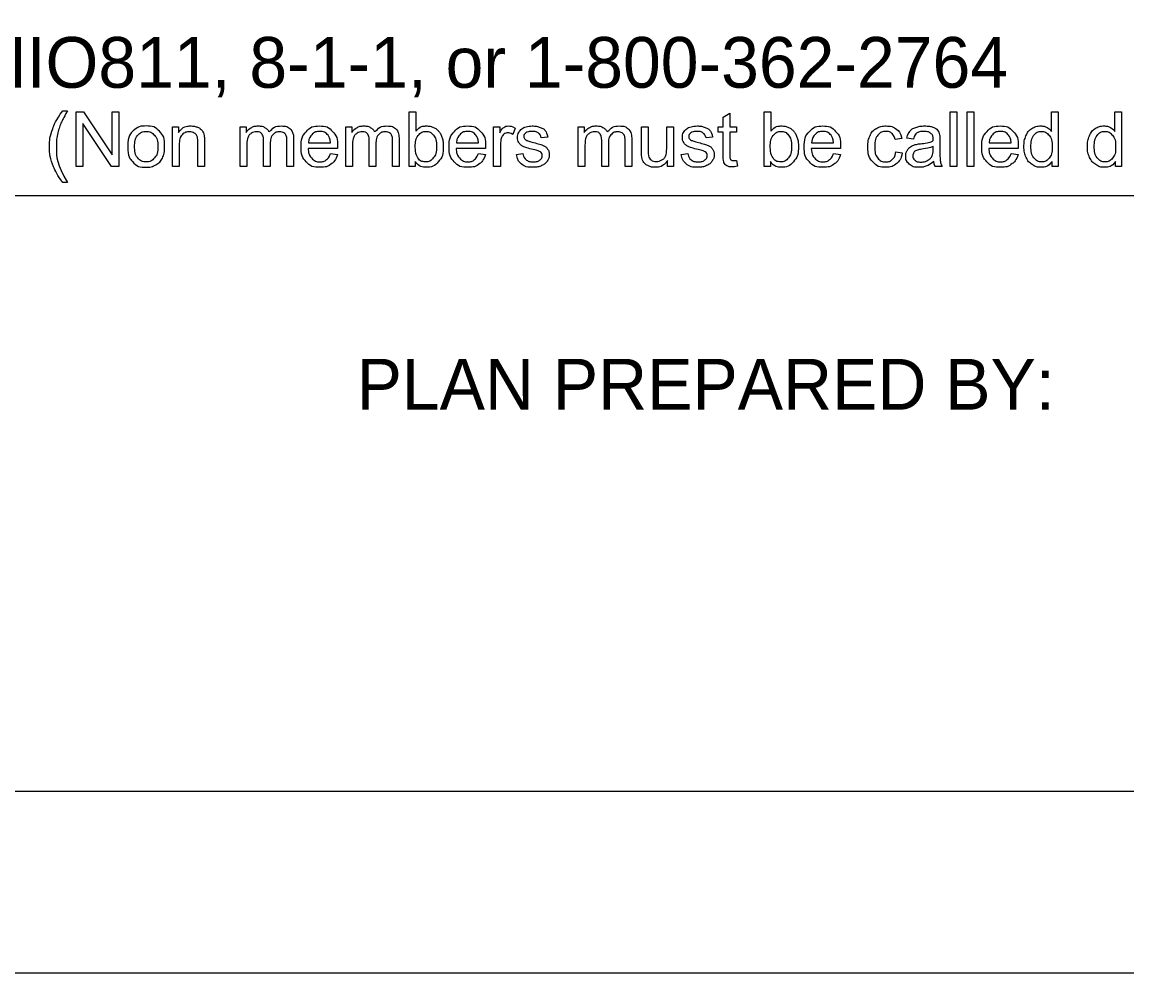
# Model space of a CAD drawing. Extents: x 0 to 34, y -1.6 to 22.
# Drawn here: x 2.69 to 5.736, y 0 to 2.622 of the extents above; entities that cross this region are included whole.
import ezdxf

# ---------------------------------------------------------------- set-up
doc = ezdxf.new("R2010")
doc.units = 0
for name, color, linetype in [('SH_Border', 7, 'Continuous'), ('SH_Cut_Line', 7, 'Continuous'), ('SH_Data', 7, 'Continuous'), ('SH_Text', 7, 'Continuous')]:
    doc.layers.add(name, color=color, linetype=linetype)

msp = doc.modelspace()

# ---------------------------------------------------------------- linework, layer by layer
at = {"layer": 'SH_Border'}
msp.add_lwpolyline([(1.5, 21.5), (33.5, 21.5), (33.5, 0.5), (1.5, 0.5)], close=True, dxfattribs=at)
at = {"layer": 'SH_Cut_Line'}
msp.add_lwpolyline([(0, 0), (34, 0), (34, 22), (0, 22)], close=True, dxfattribs=at)
at = {"layer": 'SH_Data'}
msp.add_line((6.6275, 2.1428), (2.3775, 2.1428), dxfattribs=at)
at = {"layer": 'SH_Text'}
for points in [[(2.8021, 2.3766), (2.8153, 2.3766)], [(2.8389, 2.2239), (2.8389, 2.3741), (2.8592, 2.3741), (2.9382, 2.2561), (2.9382, 2.3741), (2.9572, 2.3741), (2.9572, 2.2239), (2.9369, 2.2239), (2.8579, 2.3419), (2.8579, 2.2239), (2.8389, 2.2239)], [(3.7743, 2.2239), (3.7573, 2.2239), (3.7573, 2.3741), (3.7757, 2.3741), (3.7757, 2.3206)], [(4.6233, 2.2558), (4.6233, 2.3185), (4.6097, 2.3185), (4.6097, 2.3328), (4.6233, 2.3328), (4.6233, 2.3597), (4.6417, 2.3708), (4.6417, 2.3328), (4.6601, 2.3328), (4.6601, 2.3185), (4.6417, 2.3185), (4.6417, 2.2547)], [(4.7534, 2.2239), (4.7363, 2.2239), (4.7363, 2.3741), (4.7548, 2.3741), (4.7548, 2.3206)], [(5.2491, 2.2239), (5.2491, 2.3741), (5.2675, 2.3741), (5.2675, 2.2239), (5.2491, 2.2239)], [(5.2956, 2.2239), (5.2956, 2.3741), (5.3141, 2.3741), (5.3141, 2.2239), (5.2956, 2.2239)], [(5.5285, 2.3202), (5.5285, 2.3741), (5.5469, 2.3741), (5.5469, 2.2239), (5.5299, 2.2239)], [(5.7034, 2.3202), (5.7034, 2.3741), (5.7218, 2.3741), (5.7218, 2.2239), (5.7048, 2.2239)], [(3.1048, 2.2239), (3.1048, 2.3328), (3.1214, 2.3328), (3.1214, 2.3173)], [(3.2912, 2.2239), (3.2912, 2.3328), (3.3077, 2.3328), (3.3077, 2.3174)], [(3.5826, 2.2239), (3.5826, 2.3328), (3.5991, 2.3328), (3.5991, 2.3174)], [(3.9904, 2.2239), (3.9904, 2.3328), (4.007, 2.3328), (4.007, 2.3163)], [(4.0495, 2.3293), (4.043, 2.3122)], [(4.2236, 2.2239), (4.2236, 2.3328), (4.2401, 2.3328), (4.2401, 2.3174)], [(4.3979, 2.2654), (4.3979, 2.3328), (4.4164, 2.3328), (4.4164, 2.2724)], [(4.4676, 2.2745), (4.4676, 2.3328), (4.4861, 2.3328), (4.4861, 2.2239), (4.4696, 2.2239)], [(3.1932, 2.2908), (3.1932, 2.2239), (3.1748, 2.2239), (3.1748, 2.2901)], [(3.3743, 2.2871), (3.3743, 2.2239), (3.3559, 2.2239), (3.3559, 2.2946)], [(3.4388, 2.2986), (3.4388, 2.2239), (3.4203, 2.2239), (3.4203, 2.2924)], [(3.4799, 2.2887), (3.5406, 2.2887)], [(3.6657, 2.2871), (3.6657, 2.2239), (3.6473, 2.2239), (3.6473, 2.2946)], [(3.7301, 2.2986), (3.7301, 2.2239), (3.7117, 2.2239), (3.7117, 2.2924)], [(3.8879, 2.2887), (3.9486, 2.2887)], [(4.1394, 2.3046), (4.1213, 2.3022)], [(4.3067, 2.2871), (4.3067, 2.2239), (4.2883, 2.2239), (4.2883, 2.2946)], [(4.3711, 2.2986), (4.3711, 2.2239), (4.3527, 2.2239), (4.3527, 2.2924)], [(4.594, 2.3046), (4.5759, 2.3022)], [(4.8669, 2.2887), (4.9277, 2.2887)], [(5.1154, 2.3007), (5.0974, 2.298)], [(5.1479, 2.2992), (5.1298, 2.3016)], [(5.2209, 2.2941), (5.2209, 2.2695)], [(5.3565, 2.2887), (5.4173, 2.2887)], [(3.1233, 2.2833), (3.1233, 2.2239), (3.1048, 2.2239)], [(3.3097, 2.2803), (3.3097, 2.2239), (3.2912, 2.2239)], [(3.56, 2.2736), (3.4788, 2.2736)], [(3.5404, 2.2591), (3.5595, 2.2567)], [(3.601, 2.2803), (3.601, 2.2239), (3.5826, 2.2239)], [(3.968, 2.2736), (3.8868, 2.2736)], [(3.9484, 2.2591), (3.9675, 2.2567)], [(4.0088, 2.2809), (4.0088, 2.2239), (3.9904, 2.2239)], [(4.053, 2.2564), (4.0712, 2.2593)], [(4.242, 2.2803), (4.242, 2.2239), (4.2236, 2.2239)], [(4.5076, 2.2564), (4.5258, 2.2593)], [(4.947, 2.2736), (4.8659, 2.2736)], [(4.9275, 2.2591), (4.9465, 2.2567)], [(5.099, 2.2638), (5.1171, 2.2613)], [(5.2023, 2.2718), (5.2024, 2.2785)], [(5.4366, 2.2736), (5.3555, 2.2736)], [(5.4171, 2.2591), (5.4361, 2.2567)], [(3.7743, 2.2375), (3.7743, 2.2239)], [(4.4696, 2.2239), (4.4696, 2.24)], [(4.6601, 2.2404), (4.6628, 2.2241)], [(4.7534, 2.2375), (4.7534, 2.2239)], [(5.2267, 2.2239), (5.2075, 2.2239)], [(5.5299, 2.2239), (5.5299, 2.2376)], [(5.7048, 2.2239), (5.7048, 2.2376)], [(2.8153, 2.1798), (2.8021, 2.1798)]]:
    msp.add_lwpolyline(points, dxfattribs=at)
for points, degree in [([(2.8021, 2.1798), (2.7869, 2.199), (2.7763, 2.2248), (2.7657, 2.2506), (2.7657, 2.2783), (2.7657, 2.3026), (2.7736, 2.325), (2.7829, 2.3509), (2.8021, 2.3766)], 3), ([(2.8153, 2.3766), (2.8029, 2.3553), (2.7989, 2.3462), (2.7927, 2.332), (2.7891, 2.3167), (2.7847, 2.2975), (2.7847, 2.2782), (2.7847, 2.2289), (2.8153, 2.1798)], 3), ([(2.9814, 2.2783), (2.9814, 2.3085), (2.9981, 2.3231), (3.0122, 2.3352), (3.0323, 2.3352), (3.0547, 2.3352), (3.069, 2.3205), (3.0832, 2.3058), (3.0832, 2.2799), (3.0832, 2.2589), (3.0769, 2.2469), (3.0706, 2.2348), (3.0586, 2.2282), (3.0466, 2.2215), (3.0323, 2.2215), (3.0095, 2.2215), (2.9954, 2.2362), (2.9814, 2.2508), (2.9814, 2.2783)], 3), ([(3.0003, 2.2783), (3.0003, 2.2574), (3.0094, 2.247), (3.0185, 2.2366), (3.0323, 2.2366), (3.046, 2.2366), (3.0551, 2.2471), (3.0642, 2.2575), (3.0642, 2.279), (3.0642, 2.2991), (3.0551, 2.3095), (3.0459, 2.3199), (3.0323, 2.3199), (3.0185, 2.3199), (3.0094, 2.3096), (3.0003, 2.2992), (3.0003, 2.2783)], 3), ([(3.1214, 2.3173), (3.1334, 2.3352), (3.156, 2.3352), (3.1659, 2.3352), (3.1741, 2.3316), (3.1823, 2.3281), (3.1864, 2.3224), (3.1905, 2.3166), (3.1922, 2.3087), (3.1932, 2.3036), (3.1932, 2.2908)], 3), ([(3.1748, 2.2901), (3.1748, 2.3013), (3.1726, 2.3069), (3.1705, 2.3125), (3.165, 2.3158), (3.1595, 2.3191), (3.1521, 2.3191), (3.1404, 2.3191), (3.1318, 2.3117), (3.1233, 2.3042), (3.1233, 2.2833)], 3), ([(3.3077, 2.3174), (3.3128, 2.3254), (3.3214, 2.3303), (3.3299, 2.3352), (3.3407, 2.3352), (3.3528, 2.3352), (3.3606, 2.3301), (3.3683, 2.3251), (3.3715, 2.3161), (3.3844, 2.3352), (3.4051, 2.3352), (3.4213, 2.3352), (3.43, 2.3262), (3.4388, 2.3172), (3.4388, 2.2986)], 3), ([(3.3559, 2.2946), (3.3559, 2.3069), (3.3514, 2.313), (3.3469, 2.3191), (3.3366, 2.3191), (3.3288, 2.3191), (3.3222, 2.315), (3.3156, 2.311), (3.3126, 2.3031), (3.3097, 2.2952), (3.3097, 2.2803)], 3), ([(3.4203, 2.2924), (3.4203, 2.3035), (3.4185, 2.3083), (3.4168, 2.3132), (3.412, 2.3162), (3.4073, 2.3191), (3.401, 2.3191), (3.3895, 2.3191), (3.3819, 2.3115), (3.3743, 2.3039), (3.3743, 2.2871)], 3), ([(3.5595, 2.2567), (3.555, 2.24), (3.5428, 2.2307), (3.5306, 2.2215), (3.5117, 2.2215), (3.4878, 2.2215), (3.4738, 2.2362), (3.4598, 2.2509), (3.4598, 2.2774), (3.4598, 2.3049), (3.474, 2.32), (3.4881, 2.3352), (3.5106, 2.3352), (3.5324, 2.3352), (3.5463, 2.3203), (3.5601, 2.3055), (3.5601, 2.2785), (3.5601, 2.2769), (3.56, 2.2736)], 3), ([(3.5406, 2.2887), (3.5394, 2.3025), (3.5337, 2.3094), (3.5249, 2.3201), (3.5108, 2.3201), (3.4981, 2.3201), (3.4894, 2.3115), (3.4808, 2.303), (3.4799, 2.2887)], 3), ([(3.5991, 2.3174), (3.6042, 2.3254), (3.6127, 2.3303), (3.6212, 2.3352), (3.6321, 2.3352), (3.6442, 2.3352), (3.6519, 2.3301), (3.6597, 2.3251), (3.6628, 2.3161), (3.6758, 2.3352), (3.6965, 2.3352), (3.7127, 2.3352), (3.7214, 2.3262), (3.7301, 2.3172), (3.7301, 2.2986)], 3), ([(3.6473, 2.2946), (3.6473, 2.3069), (3.6428, 2.313), (3.6383, 2.3191), (3.628, 2.3191), (3.6202, 2.3191), (3.6136, 2.315), (3.607, 2.311), (3.604, 2.3031), (3.601, 2.2952), (3.601, 2.2803)], 3), ([(3.7117, 2.2924), (3.7117, 2.3035), (3.7099, 2.3083), (3.7081, 2.3132), (3.7034, 2.3162), (3.6987, 2.3191), (3.6923, 2.3191), (3.6809, 2.3191), (3.6733, 2.3115), (3.6657, 2.3039), (3.6657, 2.2871)], 3), ([(3.7741, 2.2792), (3.7741, 2.2596), (3.7794, 2.2509), (3.7881, 2.2366), (3.8029, 2.2366), (3.815, 2.2366), (3.8238, 2.2471), (3.8326, 2.2576), (3.8326, 2.2784), (3.8326, 2.2998), (3.8241, 2.3099), (3.8157, 2.3201), (3.8038, 2.3201), (3.7917, 2.3201), (3.7829, 2.3096), (3.7741, 2.299), (3.7741, 2.2792)], 3), ([(3.7757, 2.3206), (3.7874, 2.3352), (3.8055, 2.3352), (3.8155, 2.3352), (3.8245, 2.3311), (3.8335, 2.3271), (3.8392, 2.3198), (3.845, 2.3124), (3.8483, 2.3021), (3.8516, 2.2918), (3.8516, 2.28), (3.8516, 2.252), (3.8378, 2.2368), (3.8239, 2.2215), (3.8046, 2.2215), (3.7853, 2.2215), (3.7743, 2.2375)], 3), ([(3.9675, 2.2567), (3.963, 2.24), (3.9508, 2.2307), (3.9386, 2.2215), (3.9196, 2.2215), (3.8958, 2.2215), (3.8818, 2.2362), (3.8678, 2.2509), (3.8678, 2.2774), (3.8678, 2.3049), (3.882, 2.32), (3.8961, 2.3352), (3.9186, 2.3352), (3.9404, 2.3352), (3.9543, 2.3203), (3.9681, 2.3055), (3.9681, 2.2785), (3.9681, 2.2769), (3.968, 2.2736)], 3), ([(3.9486, 2.2887), (3.9474, 2.3025), (3.9417, 2.3094), (3.9328, 2.3201), (3.9188, 2.3201), (3.9061, 2.3201), (3.8974, 2.3115), (3.8888, 2.303), (3.8879, 2.2887)], 3), ([(4.007, 2.3163), (4.0133, 2.3278), (4.0187, 2.3315), (4.0241, 2.3352), (4.0305, 2.3352), (4.0398, 2.3352), (4.0495, 2.3293)], 3), ([(4.043, 2.3122), (4.0363, 2.3162), (4.0295, 2.3162), (4.0235, 2.3162), (4.0187, 2.3125), (4.0139, 2.3089), (4.0119, 2.3024), (4.0088, 2.2926), (4.0088, 2.2809)], 3), ([(4.1213, 2.3022), (4.1201, 2.3106), (4.1142, 2.3153), (4.1083, 2.3201), (4.0975, 2.3201), (4.0848, 2.3201), (4.0794, 2.3159), (4.0739, 2.3116), (4.0739, 2.306), (4.0739, 2.3024), (4.0762, 2.2995), (4.0785, 2.2966), (4.0833, 2.2946), (4.086, 2.2936), (4.0996, 2.2899), (4.1192, 2.2847), (4.1269, 2.2813), (4.1347, 2.278), (4.1391, 2.2717), (4.1435, 2.2653), (4.1435, 2.2559), (4.1435, 2.2467), (4.1381, 2.2386), (4.1327, 2.2304), (4.1226, 2.226), (4.1124, 2.2215), (4.0996, 2.2215), (4.0784, 2.2215), (4.0672, 2.2303), (4.0561, 2.2391), (4.053, 2.2564)], 3), ([(4.0712, 2.2593), (4.0727, 2.2483), (4.0798, 2.2425), (4.0868, 2.2366), (4.0995, 2.2366), (4.1122, 2.2366), (4.1184, 2.2418), (4.1245, 2.247), (4.1245, 2.254), (4.1245, 2.2602), (4.1191, 2.2638), (4.1153, 2.2663), (4.1002, 2.2701), (4.0799, 2.2752), (4.072, 2.2789), (4.0642, 2.2827), (4.0601, 2.2893), (4.0561, 2.2959), (4.0561, 2.3038), (4.0561, 2.3111), (4.0594, 2.3173), (4.0628, 2.3235), (4.0685, 2.3276), (4.0728, 2.3308), (4.0803, 2.333), (4.0877, 2.3352), (4.0962, 2.3352), (4.109, 2.3352), (4.1187, 2.3315), (4.1284, 2.3278), (4.133, 2.3215), (4.1377, 2.3152), (4.1394, 2.3046)], 3), ([(4.2401, 2.3174), (4.2452, 2.3254), (4.2537, 2.3303), (4.2622, 2.3352), (4.2731, 2.3352), (4.2852, 2.3352), (4.2929, 2.3301), (4.3007, 2.3251), (4.3038, 2.3161), (4.3168, 2.3352), (4.3375, 2.3352), (4.3537, 2.3352), (4.3624, 2.3262), (4.3711, 2.3172), (4.3711, 2.2986)], 3), ([(4.2883, 2.2946), (4.2883, 2.3069), (4.2838, 2.313), (4.2793, 2.3191), (4.269, 2.3191), (4.2612, 2.3191), (4.2546, 2.315), (4.248, 2.311), (4.245, 2.3031), (4.242, 2.2952), (4.242, 2.2803)], 3), ([(4.3527, 2.2924), (4.3527, 2.3035), (4.3509, 2.3083), (4.3491, 2.3132), (4.3444, 2.3162), (4.3397, 2.3191), (4.3333, 2.3191), (4.3219, 2.3191), (4.3143, 2.3115), (4.3067, 2.3039), (4.3067, 2.2871)], 3), ([(4.5759, 2.3022), (4.5747, 2.3106), (4.5688, 2.3153), (4.5629, 2.3201), (4.5521, 2.3201), (4.5394, 2.3201), (4.5339, 2.3159), (4.5285, 2.3116), (4.5285, 2.306), (4.5285, 2.3024), (4.5308, 2.2995), (4.533, 2.2966), (4.5378, 2.2946), (4.5406, 2.2936), (4.5542, 2.2899), (4.5737, 2.2847), (4.5815, 2.2813), (4.5893, 2.278), (4.5937, 2.2717), (4.5981, 2.2653), (4.5981, 2.2559), (4.5981, 2.2467), (4.5927, 2.2386), (4.5873, 2.2304), (4.5772, 2.226), (4.567, 2.2215), (4.5542, 2.2215), (4.5329, 2.2215), (4.5218, 2.2303), (4.5107, 2.2391), (4.5076, 2.2564)], 3), ([(4.5258, 2.2593), (4.5273, 2.2483), (4.5343, 2.2425), (4.5414, 2.2366), (4.554, 2.2366), (4.5668, 2.2366), (4.5729, 2.2418), (4.5791, 2.247), (4.5791, 2.254), (4.5791, 2.2602), (4.5736, 2.2638), (4.5698, 2.2663), (4.5548, 2.2701), (4.5345, 2.2752), (4.5266, 2.2789), (4.5188, 2.2827), (4.5147, 2.2893), (4.5107, 2.2959), (4.5107, 2.3038), (4.5107, 2.3111), (4.514, 2.3173), (4.5173, 2.3235), (4.5231, 2.3276), (4.5274, 2.3308), (4.5348, 2.333), (4.5423, 2.3352), (4.5508, 2.3352), (4.5636, 2.3352), (4.5733, 2.3315), (4.583, 2.3278), (4.5876, 2.3215), (4.5922, 2.3152), (4.594, 2.3046)], 3), ([(4.7532, 2.2792), (4.7532, 2.2596), (4.7585, 2.2509), (4.7672, 2.2366), (4.782, 2.2366), (4.7941, 2.2366), (4.8029, 2.2471), (4.8116, 2.2576), (4.8116, 2.2784), (4.8116, 2.2998), (4.8032, 2.3099), (4.7948, 2.3201), (4.7828, 2.3201), (4.7708, 2.3201), (4.762, 2.3096), (4.7532, 2.299), (4.7532, 2.2792)], 3), ([(4.7548, 2.3206), (4.7664, 2.3352), (4.7846, 2.3352), (4.7946, 2.3352), (4.8036, 2.3311), (4.8125, 2.3271), (4.8183, 2.3198), (4.8241, 2.3124), (4.8274, 2.3021), (4.8306, 2.2918), (4.8306, 2.28), (4.8306, 2.252), (4.8168, 2.2368), (4.803, 2.2215), (4.7836, 2.2215), (4.7644, 2.2215), (4.7534, 2.2375)], 3), ([(4.9465, 2.2567), (4.942, 2.24), (4.9298, 2.2307), (4.9177, 2.2215), (4.8987, 2.2215), (4.8749, 2.2215), (4.8609, 2.2362), (4.8469, 2.2509), (4.8469, 2.2774), (4.8469, 2.3049), (4.861, 2.32), (4.8752, 2.3352), (4.8977, 2.3352), (4.9195, 2.3352), (4.9333, 2.3203), (4.9471, 2.3055), (4.9471, 2.2785), (4.9471, 2.2769), (4.947, 2.2736)], 3), ([(4.9277, 2.2887), (4.9265, 2.3025), (4.9207, 2.3094), (4.9119, 2.3201), (4.8979, 2.3201), (4.8852, 2.3201), (4.8765, 2.3115), (4.8678, 2.303), (4.8669, 2.2887)], 3), ([(5.1171, 2.2613), (5.1141, 2.2427), (5.1019, 2.2321), (5.0896, 2.2215), (5.0718, 2.2215), (5.0495, 2.2215), (5.0359, 2.2361), (5.0223, 2.2507), (5.0223, 2.2779), (5.0223, 2.2955), (5.0282, 2.3088), (5.034, 2.322), (5.046, 2.3286), (5.0579, 2.3352), (5.0719, 2.3352), (5.0897, 2.3352), (5.1009, 2.3262), (5.1122, 2.3172), (5.1154, 2.3007)], 3), ([(5.0974, 2.298), (5.0949, 2.309), (5.0884, 2.3145), (5.0819, 2.3201), (5.0726, 2.3201), (5.0587, 2.3201), (5.05, 2.3101), (5.0413, 2.3001), (5.0413, 2.2784), (5.0413, 2.2565), (5.0497, 2.2466), (5.0581, 2.2366), (5.0717, 2.2366), (5.0825, 2.2366), (5.0898, 2.2433), (5.0971, 2.2499), (5.099, 2.2638)], 3), ([(5.2038, 2.2373), (5.1936, 2.2287), (5.1841, 2.2251), (5.1746, 2.2215), (5.1638, 2.2215), (5.1458, 2.2215), (5.1362, 2.2303), (5.1266, 2.239), (5.1266, 2.2526), (5.1266, 2.2606), (5.1302, 2.2672), (5.1339, 2.2738), (5.1398, 2.2778), (5.1456, 2.2818), (5.153, 2.2838), (5.1584, 2.2853), (5.1694, 2.2866), (5.1917, 2.2893), (5.2023, 2.2929), (5.2024, 2.2967), (5.2024, 2.2978), (5.2024, 2.3091), (5.1971, 2.3137), (5.1901, 2.3199), (5.1762, 2.3199), (5.1632, 2.3199), (5.157, 2.3154), (5.1508, 2.3108), (5.1479, 2.2992)], 3), ([(5.1298, 2.3016), (5.1323, 2.3132), (5.1379, 2.3203), (5.1435, 2.3275), (5.1542, 2.3313), (5.1648, 2.3352), (5.1788, 2.3352), (5.1928, 2.3352), (5.2015, 2.3319), (5.2102, 2.3286), (5.2142, 2.3236), (5.2183, 2.3187), (5.22, 2.3111), (5.2209, 2.3064), (5.2209, 2.2941)], 3), ([(5.4361, 2.2567), (5.4316, 2.24), (5.4194, 2.2307), (5.4072, 2.2215), (5.3883, 2.2215), (5.3644, 2.2215), (5.3505, 2.2362), (5.3365, 2.2509), (5.3365, 2.2774), (5.3365, 2.3049), (5.3506, 2.32), (5.3648, 2.3352), (5.3873, 2.3352), (5.4091, 2.3352), (5.4229, 2.3203), (5.4367, 2.3055), (5.4367, 2.2785), (5.4367, 2.2769), (5.4366, 2.2736)], 3), ([(5.4173, 2.2887), (5.4161, 2.3025), (5.4103, 2.3094), (5.4015, 2.3201), (5.3875, 2.3201), (5.3748, 2.3201), (5.3661, 2.3115), (5.3574, 2.303), (5.3565, 2.2887)], 3), ([(5.5299, 2.2376), (5.5195, 2.2215), (5.4995, 2.2215), (5.4865, 2.2215), (5.4755, 2.2287), (5.4646, 2.2359), (5.4586, 2.2487), (5.4526, 2.2616), (5.4526, 2.2782), (5.4526, 2.2945), (5.4581, 2.3078), (5.4635, 2.321), (5.4743, 2.3281), (5.4852, 2.3352), (5.4986, 2.3352), (5.5084, 2.3352), (5.516, 2.331), (5.5237, 2.3269), (5.5285, 2.3202)], 3), ([(5.4716, 2.2782), (5.4716, 2.2573), (5.4805, 2.247), (5.4893, 2.2366), (5.5012, 2.2366), (5.5133, 2.2366), (5.5218, 2.2465), (5.5302, 2.2564), (5.5302, 2.2767), (5.5302, 2.299), (5.5216, 2.3095), (5.513, 2.3199), (5.5004, 2.3199), (5.4881, 2.3199), (5.4799, 2.3099), (5.4716, 2.2999), (5.4716, 2.2782)], 3), ([(5.7048, 2.2376), (5.6944, 2.2215), (5.6743, 2.2215), (5.6613, 2.2215), (5.6504, 2.2287), (5.6395, 2.2359), (5.6335, 2.2487), (5.6275, 2.2616), (5.6275, 2.2782), (5.6275, 2.2945), (5.6329, 2.3078), (5.6384, 2.321), (5.6492, 2.3281), (5.66, 2.3352), (5.6734, 2.3352), (5.6832, 2.3352), (5.6909, 2.331), (5.6986, 2.3269), (5.7034, 2.3202)], 3), ([(5.6465, 2.2782), (5.6465, 2.2573), (5.6553, 2.247), (5.6641, 2.2366), (5.6761, 2.2366), (5.6882, 2.2366), (5.6967, 2.2465), (5.7051, 2.2564), (5.7051, 2.2767), (5.7051, 2.299), (5.6965, 2.3095), (5.6879, 2.3199), (5.6753, 2.3199), (5.663, 2.3199), (5.6548, 2.3099), (5.6465, 2.2999), (5.6465, 2.2782)], 3), ([(3.4788, 2.2736), (3.4799, 2.2557), (3.489, 2.2462), (3.4981, 2.2366), (3.5117, 2.2366), (3.5219, 2.2366), (3.5291, 2.242), (3.5362, 2.2473), (3.5404, 2.2591)], 3), ([(3.8868, 2.2736), (3.8879, 2.2557), (3.897, 2.2462), (3.9061, 2.2366), (3.9197, 2.2366), (3.9299, 2.2366), (3.937, 2.242), (3.9442, 2.2473), (3.9484, 2.2591)], 3), ([(4.4696, 2.24), (4.4569, 2.2215), (4.4351, 2.2215), (4.4255, 2.2215), (4.4171, 2.2252), (4.4088, 2.2289), (4.4047, 2.2345), (4.4007, 2.2401), (4.3991, 2.2482), (4.3979, 2.2536), (4.3979, 2.2654)], 3), ([(4.4164, 2.2724), (4.4164, 2.258), (4.4175, 2.253), (4.4192, 2.2457), (4.4249, 2.2416), (4.4305, 2.2374), (4.4388, 2.2374), (4.4471, 2.2374), (4.4543, 2.2417), (4.4616, 2.2459), (4.4646, 2.2533), (4.4676, 2.2606), (4.4676, 2.2745)], 3), ([(4.6628, 2.2241), (4.655, 2.2224), (4.6488, 2.2224), (4.6388, 2.2224), (4.6333, 2.2256), (4.6278, 2.2288), (4.6255, 2.234), (4.6233, 2.2392), (4.6233, 2.2558)], 3), ([(4.6417, 2.2547), (4.6417, 2.2468), (4.6427, 2.2445), (4.6436, 2.2423), (4.6458, 2.2409), (4.648, 2.2396), (4.6521, 2.2396), (4.6551, 2.2396), (4.6601, 2.2404)], 3), ([(4.8659, 2.2736), (4.8669, 2.2557), (4.876, 2.2462), (4.8852, 2.2366), (4.8988, 2.2366), (4.9089, 2.2366), (4.9161, 2.242), (4.9233, 2.2473), (4.9275, 2.2591)], 3), ([(5.2024, 2.2785), (5.1923, 2.2744), (5.1722, 2.2716), (5.1608, 2.2699), (5.1561, 2.2679), (5.1514, 2.2658), (5.1488, 2.2619), (5.1463, 2.2579), (5.1463, 2.2531), (5.1463, 2.2458), (5.1519, 2.2409), (5.1574, 2.2359), (5.1682, 2.2359), (5.1788, 2.2359), (5.1871, 2.2406), (5.1954, 2.2453), (5.1993, 2.2533), (5.2023, 2.2596), (5.2023, 2.2718)], 3), ([(5.2209, 2.2695), (5.2209, 2.2438), (5.2221, 2.237), (5.2233, 2.2302), (5.2267, 2.2239)], 3), ([(5.3555, 2.2736), (5.3565, 2.2557), (5.3656, 2.2462), (5.3748, 2.2366), (5.3884, 2.2366), (5.3985, 2.2366), (5.4057, 2.242), (5.4129, 2.2473), (5.4171, 2.2591)], 3), ([(5.2075, 2.2239), (5.2047, 2.2296), (5.2038, 2.2373)], 2)]:
    msp.add_open_spline(points, degree=degree, dxfattribs=at)

# ---------------------------------------------------------------- texts
for s, p in [('OHIO811, 8-1-1, or 1-800-362-2764', (2.422, 2.4406)), ('PLAN PREPARED BY:', (3.6125, 1.553))]:
    msp.add_text(s, height=0.14, dxfattribs=at).set_placement(p)

doc.saveas('drawing.dxf')
